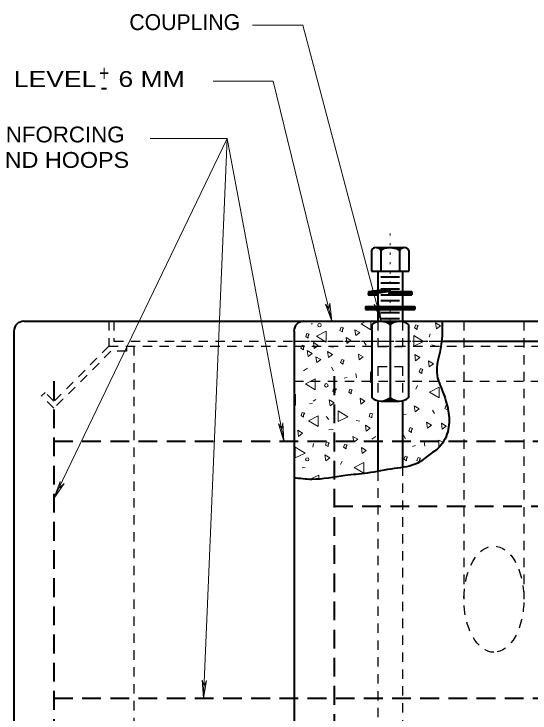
# Model space of a CAD drawing. Extents: x 312583 to 312854, y 144419 to 144597.
# Drawn here: x 312622.62 to 312647.35, y 144453.61 to 144487.12 of the extents above; entities that cross this region are included whole.
import ezdxf

# ---------------------------------------------------------------- set-up
doc = ezdxf.new("R2010")
doc.units = 0
doc.header["$LTSCALE"] = 0.3
for name, pattern in [('DOTTED', [1.5, 0.3, -1.2]), ('MEDIUM_DASHED', [4.5, 3, -1.5]), ('SHORT_DASHED', [2.7, 1.5, -1.2])]:
    doc.linetypes.add(name, pattern=pattern)
doc.layers.add('1', color=7, linetype='Continuous', lineweight=13)

msp = doc.modelspace()

# ---------------------------------------------------------------- linework, layer by layer
at = {"layer": '1'}
for p, q in [((312636.46, 144486.5936), (312634.0486, 144486.5936)), ((312636.46, 144486.5936), (312640.2097, 144472.3914)), ((312635.0366, 144483.8976), (312632.1687, 144483.8976)), ((312635.0366, 144483.8976), (312637.856, 144472.3914)), ((312632.8382, 144481.1516), (312624.539, 144463.8891)), ((312632.8382, 144481.1516), (312629.1475, 144481.1516)), ((312632.8382, 144481.1516), (312631.6997, 144454.3134)), ((312632.8382, 144481.1516), (312635.556, 144466.6414)), ((312637.5528, 144473.2095), (312637.7151, 144472.9649)), ((312637.852, 144472.3891), (312637.5528, 144473.2095)), ((312637.7562, 144473.2557), (312637.7151, 144472.9649)), ((312637.852, 144472.3891), (312637.7562, 144473.2557)), ((312639.8758, 144473.2008), (312640.0527, 144472.9636)), ((312640.2109, 144472.3948), (312639.8758, 144473.2008)), ((312640.0881, 144473.2553), (312640.0527, 144472.9636)), ((312640.2109, 144472.3948), (312640.0881, 144473.2553)), ((312636.8594, 144472.2611), (312636.9207, 144472.2611)), ((312639.7267, 144471.9851), (312639.7267, 144472.3914)), ((312642.571, 144471.7858), (312642.5097, 144471.6324)), ((312637.7947, 144471.1571), (312637.948, 144471.1724)), ((312639.397, 144471.3948), (312639.4967, 144471.2491)), ((312642.64, 144471.2568), (312642.8087, 144471.2184)), ((312641.5284, 144470.8044), (312641.536, 144470.8044)), ((312637.833, 144470.1834), (312637.925, 144470.0148)), ((312636.683, 144470.1374), (312636.499, 144470.0071)), ((312639.006, 144469.8921), (312639.029, 144469.6774)), ((312639.7727, 144469.9304), (312639.7114, 144469.9688)), ((312638.4387, 144469.6544), (312638.5844, 144469.7004)), ((312641.9577, 144469.3094), (312641.881, 144469.1331)), ((312636.9514, 144468.5658), (312637.0817, 144468.6348)), ((312636.0544, 144468.4048), (312636.108, 144468.3741)), ((312636.7827, 144468.4278), (312636.9284, 144468.4584)), ((312643.3914, 144468.2514), (312643.399, 144468.2591)), ((312637.5877, 144467.8298), (312637.7104, 144467.6764)), ((312641.2677, 144467.9218), (312641.421, 144467.9371)), ((312642.6707, 144468.1211), (312642.7704, 144467.9754)), ((312635.5083, 144467.5166), (312635.4538, 144467.2303)), ((312635.5524, 144466.647), (312635.5083, 144467.5166)), ((312639.0214, 144467.6381), (312639.19, 144467.5998)), ((312635.3005, 144467.4807), (312635.4538, 144467.2303)), ((312635.5524, 144466.647), (312635.3005, 144467.4807)), ((312637.7027, 144467.1781), (312637.9174, 144467.1934)), ((312639.9567, 144466.8714), (312639.7727, 144466.7334)), ((312641.2907, 144466.9251), (312641.3827, 144466.7488)), ((312636.9437, 144466.3501), (312636.9667, 144466.5341)), ((312642.2797, 144466.6184), (312642.3027, 144466.4038)), ((312642.985, 144466.6951), (312642.985, 144466.3654)), ((312643.169, 144466.5878), (312642.985, 144466.6951)), ((312641.7124, 144466.3808), (312641.858, 144466.4268)), ((312638.339, 144465.6908), (312638.27, 144465.5221)), ((312642.0574, 144465.6754), (312642.0574, 144465.7444)), ((312636.43, 144465.3688), (312636.5757, 144465.3764)), ((312624.539, 144463.8891), (312624.8304, 144464.7094)), ((312624.539, 144463.8891), (312625.022, 144464.6098)), ((312624.8304, 144464.7094), (312624.8074, 144464.4104)), ((312625.022, 144464.6098), (312624.8074, 144464.4104)), ((312631.6387, 144455.1846), (312631.731, 144454.9032)), ((312631.6991, 144454.3137), (312631.6387, 144455.1846)), ((312631.6991, 144454.3137), (312631.853, 144455.173)), ((312631.853, 144455.173), (312631.731, 144454.9032))]:
    msp.add_line(p, q, dxfattribs=at)
at = {"layer": '1', "linetype": 'DOTTED'}
msp.add_line((312640.6467, 144476.6004), (312640.6467, 144472.3914), dxfattribs=at)
at = {"layer": '1', "lineweight": 40}
for p, q in [((312639.972, 144475.9258), (312641.3214, 144475.9258)), ((312639.7497, 144475.7878), (312639.7497, 144474.7911)), ((312640.202, 144475.7878), (312640.202, 144474.7911)), ((312641.099, 144475.7878), (312641.099, 144474.7911)), ((312641.5437, 144475.7878), (312641.5437, 144474.7911)), ((312639.7497, 144474.7911), (312641.5437, 144474.7911)), ((312640.0487, 144474.7911), (312640.0487, 144472.3914)), ((312641.2447, 144474.7911), (312641.2447, 144472.3914)), ((312640.202, 144474.5151), (312641.099, 144474.5151)), ((312640.202, 144474.2314), (312641.099, 144474.2314)), ((312640.202, 144473.9478), (312641.099, 144473.9478)), ((312639.6117, 144473.8098), (312639.6117, 144473.6641)), ((312640.202, 144473.6641), (312641.099, 144473.6641)), ((312640.5624, 144473.6641), (312641.6894, 144473.6641)), ((312640.6007, 144473.8098), (312641.6894, 144473.8098)), ((312641.6894, 144473.8021), (312641.6894, 144473.6641)), ((312640.202, 144473.3804), (312641.099, 144473.3804)), ((312639.466, 144473.0968), (312641.8274, 144473.0968)), ((312639.466, 144473.0968), (312639.466, 144472.9588)), ((312639.466, 144473.0661), (312641.8274, 144473.0661)), ((312639.466, 144473.0278), (312641.8274, 144473.0278)), ((312639.466, 144472.9894), (312641.8274, 144472.9894)), ((312639.466, 144472.9588), (312641.8274, 144472.9588)), ((312641.8274, 144473.0968), (312641.8274, 144472.9588)), ((312640.202, 144472.8131), (312641.099, 144472.8131)), ((312640.202, 144472.5294), (312641.099, 144472.5294)), ((312623.0977, 144472.3914), (312636.5144, 144472.3914)), ((312636.5144, 144472.3914), (312654.7227, 144472.3914)), ((312639.7727, 144472.2304), (312639.7727, 144468.7268)), ((312640.0487, 144472.3914), (312641.2447, 144472.3914)), ((312640.2097, 144472.3914), (312641.0837, 144472.3914)), ((312640.6467, 144472.3914), (312640.6467, 144468.5658)), ((312641.5284, 144472.2304), (312641.5284, 144468.7268)), ((312622.6224, 144471.9161), (312622.6224, 144429.2664)), ((312636.039, 144471.9161), (312636.039, 144448.7628)), ((312643.0924, 144471.4331), (312648.1217, 144471.4331)), ((312640.0487, 144468.5581), (312640.0487, 144465.1924)), ((312640.2097, 144468.5658), (312641.0837, 144468.5658)), ((312641.2447, 144468.5581), (312641.2447, 144465.4224))]:
    msp.add_line(p, q, dxfattribs=at)
at = {"layer": '1', "linetype": 'SHORT_DASHED', "lineweight": 25}
for p, q in [((312627.1687, 144472.3914), (312627.1687, 144471.1954)), ((312627.414, 144472.3914), (312627.414, 144471.4331)), ((312640.0487, 144472.3914), (312640.0487, 144471.1801)), ((312641.2447, 144472.3914), (312641.2447, 144471.1801)), ((312644.181, 144472.3914), (312644.181, 144459.0668)), ((312647.056, 144472.3914), (312647.056, 144459.0668)), ((312627.1687, 144471.1954), (312624.539, 144468.5581)), ((312627.1687, 144471.1954), (312664.0684, 144471.1954)), ((312627.414, 144471.4331), (312663.8307, 144471.4331)), ((312628.012, 144471.1954), (312628.012, 144470.9578)), ((312628.3724, 144471.1954), (312628.3724, 144429.2664)), ((312636.039, 144471.4331), (312643.0924, 144471.4331)), ((312640.0487, 144471.1801), (312641.2447, 144471.1801)), ((312627.2684, 144470.9578), (312624.539, 144468.2208)), ((312628.012, 144470.9578), (312627.2684, 144470.9578)), ((312640.0487, 144470.2294), (312641.2447, 144470.2294)), ((312640.0487, 144470.2294), (312640.0487, 144468.5811)), ((312641.2447, 144470.2294), (312641.2447, 144468.5811)), ((312636.039, 144469.5164), (312655.2057, 144469.5164)), ((312624.1097, 144468.9798), (312623.941, 144468.8111)), ((312624.539, 144468.5581), (312624.1097, 144468.9798)), ((312624.539, 144468.2208), (312623.941, 144468.8111)), ((312640.0487, 144465.1924), (312640.0487, 144436.6878)), ((312641.2447, 144465.4224), (312641.2447, 144436.6878))]:
    msp.add_line(p, q, dxfattribs=at)
at = {"layer": '1', "linetype": 'MEDIUM_DASHED', "lineweight": 40}
for p, q in [((312624.539, 144469.5164), (312624.539, 144432.1414)), ((312637.9557, 144469.7541), (312637.9557, 144448.7628)), ((312624.539, 144466.6414), (312666.7057, 144466.6414)), ((312637.9557, 144463.5288), (312653.289, 144463.5288)), ((312624.539, 144454.3134), (312666.7057, 144454.3134))]:
    msp.add_line(p, q, dxfattribs=at)
at = {"layer": '1', "lineweight": 40}
for points in [[(312640.0334, 144475.9258), (312640.5317, 144475.9181), (312640.4474, 144475.9028), (312640.3937, 144475.8951), (312640.294, 144475.8568), (312640.202, 144475.7954), (312640.1714, 144475.8491), (312640.1254, 144475.8798), (312640.0487, 144475.9181), (312640.4934, 144475.9181), (312640.363, 144475.8951), (312640.2787, 144475.8491), (312640.2097, 144475.8031), (312640.133, 144475.8721), (312640.0794, 144475.9104), (312640.4397, 144475.9104), (312640.317, 144475.8721), (312640.2097, 144475.8184), (312640.11, 144475.9028), (312640.3937, 144475.9104), (312640.202, 144475.8261), (312640.1254, 144475.8951), (312640.363, 144475.9028), (312640.1944, 144475.8414), (312640.1407, 144475.8951), (312640.3324, 144475.8951), (312640.202, 144475.8568), (312640.1637, 144475.8874), (312640.2787, 144475.8874), (312640.2097, 144475.8644), (312640.1867, 144475.8798), (312640.2404, 144475.8798), (312640.202, 144475.8721)], [(312641.2677, 144475.9258), (312640.7617, 144475.9181), (312640.846, 144475.9028), (312640.9074, 144475.8951), (312640.9994, 144475.8568), (312641.0914, 144475.7954), (312641.1297, 144475.8491), (312641.168, 144475.8798), (312641.2447, 144475.9181), (312640.8, 144475.9181), (312640.9304, 144475.8951), (312641.0224, 144475.8491), (312641.0914, 144475.8031), (312641.1604, 144475.8721), (312641.214, 144475.9104), (312640.8537, 144475.9104), (312640.9764, 144475.8721), (312641.0914, 144475.8184), (312641.191, 144475.9028), (312640.8997, 144475.9104), (312641.0914, 144475.8261), (312641.168, 144475.8951), (312640.9304, 144475.9028), (312641.099, 144475.8414), (312641.1527, 144475.8951), (312640.9687, 144475.8951), (312641.0914, 144475.8568), (312641.1297, 144475.8874), (312641.0147, 144475.8874), (312641.0837, 144475.8644), (312641.1067, 144475.8798), (312641.053, 144475.8798), (312641.0914, 144475.8721)], [(312639.6117, 144473.8098), (312640.6467, 144473.9478), (312640.5624, 144473.6641)], [(312640.0487, 144473.6641), (312639.6117, 144473.6794), (312639.627, 144473.7944), (312640.616, 144473.9248), (312640.5854, 144473.8174), (312640.041, 144473.7408), (312640.0334, 144473.6871), (312639.6347, 144473.7024), (312639.6424, 144473.7714), (312640.593, 144473.9018), (312640.57, 144473.8328), (312640.018, 144473.7408), (312640.0104, 144473.7024), (312639.65, 144473.7101), (312639.65, 144473.7484), (312640.5547, 144473.8788), (312640.5547, 144473.8558), (312640.0257, 144473.7561), (312639.9874, 144473.7408), (312639.88, 144473.7178), (312639.673, 144473.7331), (312640.5317, 144473.8634), (312639.811, 144473.7254)], [(312640.6007, 144473.8098), (312639.6117, 144473.6641), (312640.0487, 144473.6641)], [(312640.5854, 144473.6794), (312641.6664, 144473.6794), (312641.6664, 144473.7944), (312640.6237, 144473.7868), (312640.5854, 144473.7024), (312641.651, 144473.6948), (312641.6434, 144473.7714), (312640.6314, 144473.7638), (312640.6084, 144473.7101), (312641.628, 144473.7178), (312641.6127, 144473.7484), (312641.605, 144473.7561), (312640.639, 144473.7484), (312640.6237, 144473.7254), (312641.605, 144473.7331)], [(312640.3247, 144472.3838), (312640.9764, 144472.3838), (312640.8997, 144472.3684), (312640.8307, 144472.3531), (312640.7617, 144472.3224), (312640.7157, 144472.2994), (312640.6544, 144472.2534), (312640.6467, 144472.2458), (312640.524, 144472.3224), (312640.4167, 144472.3684), (312640.3554, 144472.3838), (312640.9304, 144472.3838), (312640.8844, 144472.3761), (312640.8307, 144472.3608), (312640.7617, 144472.3378), (312640.6927, 144472.2994), (312640.6697, 144472.2764), (312640.6467, 144472.2534), (312640.5394, 144472.3301), (312640.4167, 144472.3761), (312640.846, 144472.3761), (312640.7387, 144472.3378), (312640.6467, 144472.2764), (312640.4627, 144472.3684), (312640.8, 144472.3684), (312640.6467, 144472.2688), (312640.501, 144472.3608), (312640.7694, 144472.3608), (312640.6544, 144472.2994), (312640.5547, 144472.3531), (312640.731, 144472.3531), (312640.6467, 144472.3224), (312640.547, 144472.3454), (312640.6084, 144472.3071), (312640.6237, 144472.3454), (312640.639, 144472.2918), (312640.685, 144472.3378), (312640.708, 144472.3378), (312640.7387, 144472.3454)], [(312640.3247, 144468.5734), (312640.9764, 144468.5658), (312640.8997, 144468.5811), (312640.8307, 144468.6041), (312640.7617, 144468.6348), (312640.7157, 144468.6578), (312640.6544, 144468.7038), (312640.6467, 144468.7114), (312640.524, 144468.6348), (312640.4167, 144468.5888), (312640.3554, 144468.5734), (312640.9304, 144468.5734), (312640.8844, 144468.5811), (312640.8307, 144468.5888), (312640.7617, 144468.6194), (312640.6927, 144468.6578), (312640.6697, 144468.6731), (312640.6467, 144468.6961), (312640.5394, 144468.6271), (312640.4167, 144468.5811), (312640.846, 144468.5811), (312640.7387, 144468.6194), (312640.6467, 144468.6731), (312640.4627, 144468.5888), (312640.8, 144468.5811), (312640.6467, 144468.6884), (312640.501, 144468.5964), (312640.7694, 144468.5888), (312640.6544, 144468.6578), (312640.5547, 144468.6041), (312640.731, 144468.6041), (312640.6467, 144468.6271), (312640.547, 144468.6118), (312640.6084, 144468.6501), (312640.6237, 144468.6118), (312640.639, 144468.6654), (312640.685, 144468.6194), (312640.708, 144468.6194), (312640.7387, 144468.6118)]]:
    msp.add_lwpolyline(points, dxfattribs=at)
at = {"layer": '1'}
for points in [[(312639.5044, 144472.3914), (312639.259, 144472.2688), (312639.7267, 144471.9851)], [(312641.5284, 144472.0618), (312641.5744, 144472.1001), (312641.5284, 144472.1308)], [(312639.7114, 144469.9688), (312639.7114, 144469.4551), (312639.7727, 144469.4781)], [(312636.108, 144468.3741), (312636.108, 144468.8878), (312636.0467, 144468.8494)], [(312643.3377, 144468.3588), (312643.3224, 144468.3664), (312643.261, 144468.2131), (312643.3914, 144468.1441), (312643.3914, 144468.2514)], [(312642.0574, 144465.7444), (312642.1034, 144465.8288), (312641.9884, 144465.8594), (312641.927, 144465.7138), (312642.0344, 144465.6524)], [(312637.235, 144464.8398), (312637.235, 144465.0161), (312636.8517, 144464.8321)]]:
    msp.add_lwpolyline(points, dxfattribs=at)
for points in [[(312641.9424, 144472.1078), (312641.996, 144472.1844), (312641.8734, 144472.2228), (312641.8197, 144472.0694), (312641.9424, 144472.0004)], [(312642.8624, 144472.0311), (312643.054, 144472.1768), (312642.8164, 144472.3148)], [(312637.58, 144471.3948), (312637.58, 144471.9084), (312637.1124, 144471.6708)], [(312638.362, 144471.9928), (312638.4157, 144472.0771), (312638.293, 144472.1078), (312638.2394, 144471.9544), (312638.362, 144471.8854)], [(312638.9984, 144471.7014), (312639.1977, 144471.8471), (312638.96, 144471.9851)], [(312636.7214, 144471.6938), (312636.7674, 144471.7781), (312636.6524, 144471.8088), (312636.5987, 144471.6554), (312636.7214, 144471.5864)], [(312638.569, 144471.3258), (312638.7607, 144471.4714), (312638.5307, 144471.6171)], [(312641.7737, 144471.7091), (312641.7737, 144471.1954), (312642.2414, 144471.4254)], [(312636.4914, 144471.1341), (312636.545, 144471.2184), (312636.4224, 144471.2491), (312636.3687, 144471.0958), (312636.4914, 144471.0268)], [(312637.0127, 144471.0804), (312637.2044, 144471.2338), (312636.9744, 144471.3718)], [(312636.7137, 144470.7048), (312636.913, 144470.8504), (312636.6754, 144470.9884)], [(312637.695, 144470.6588), (312637.8867, 144470.8044), (312637.649, 144470.9424)], [(312637.1354, 144470.4058), (312637.327, 144470.5514), (312637.0894, 144470.6894)], [(312638.4004, 144470.4441), (312638.4464, 144470.5284), (312638.3314, 144470.5591), (312638.27, 144470.4134), (312638.4004, 144470.3368)], [(312639.167, 144470.5361), (312639.3587, 144470.6818), (312639.1287, 144470.8198)], [(312641.8657, 144470.4978), (312642.065, 144470.6511), (312641.8274, 144470.7891)], [(312642.5174, 144470.2064), (312642.7167, 144470.3521), (312642.479, 144470.4901)], [(312642.1647, 144469.9994), (312642.2107, 144470.0838), (312642.0957, 144470.1221), (312642.0344, 144469.9688), (312642.1647, 144469.8921)], [(312637.0587, 144469.1101), (312637.0587, 144469.6238), (312636.591, 144469.3861)], [(312638.017, 144469.0718), (312638.0707, 144469.1561), (312637.948, 144469.1868), (312637.8944, 144469.0411), (312638.017, 144468.9644)], [(312643.0004, 144468.7191), (312643.0004, 144469.2328), (312642.5327, 144468.9951)], [(312638.7837, 144469.0181), (312638.8297, 144469.1024), (312638.7147, 144469.1331), (312638.661, 144468.9874), (312638.7837, 144468.9108)], [(312637.764, 144468.3358), (312637.9557, 144468.4814), (312637.7257, 144468.6194)], [(312639.2437, 144468.4124), (312639.4354, 144468.5581), (312639.2054, 144468.6961)], [(312641.8427, 144468.0521), (312642.0344, 144468.1978), (312641.8044, 144468.3434)], [(312636.499, 144467.9064), (312636.5527, 144467.9831), (312636.43, 144468.0214), (312636.3764, 144467.8681), (312636.499, 144467.7991)], [(312637.2044, 144467.3391), (312637.2044, 144467.8528), (312636.7367, 144467.6151)], [(312638.155, 144468.0904), (312638.155, 144467.5768), (312638.6227, 144467.8144)], [(312639.765, 144467.8604), (312639.8187, 144467.9448), (312639.696, 144467.9831), (312639.6424, 144467.8298), (312639.765, 144467.7531)], [(312642.4407, 144467.2624), (312642.6324, 144467.4081), (312642.3947, 144467.5461)], [(312643.146, 144467.2164), (312643.3377, 144467.3621), (312643.1077, 144467.5078)], [(312636.2537, 144466.8714), (312636.453, 144467.0248), (312636.2154, 144467.1628)], [(312639.4967, 144467.1244), (312639.696, 144467.2701), (312639.4584, 144467.4081)], [(312641.674, 144467.1704), (312641.72, 144467.2548), (312641.605, 144467.2931), (312641.5437, 144467.1398), (312641.674, 144467.0631)], [(312638.9064, 144466.5878), (312639.098, 144466.7334), (312638.8604, 144466.8714)], [(312637.6797, 144466.4804), (312637.7257, 144466.5648), (312637.603, 144466.6031), (312637.5494, 144466.4498), (312637.6797, 144466.3808)], [(312638.546, 144466.3808), (312638.592, 144466.4651), (312638.477, 144466.5034), (312638.4157, 144466.3501), (312638.546, 144466.2811)], [(312636.1004, 144466.3501), (312636.1004, 144465.8364), (312636.568, 144466.0664)], [(312639.3127, 144466.0511), (312639.5044, 144466.1968), (312639.2667, 144466.3348)], [(312637.557, 144465.6984), (312637.7487, 144465.8441), (312637.5187, 144465.9898)], [(312641.4287, 144465.8058), (312641.4747, 144465.8901), (312641.3597, 144465.9284), (312641.2984, 144465.7751), (312641.4287, 144465.6984)], [(312639.3817, 144465.1004), (312639.3817, 144465.6141), (312638.914, 144465.3764)]]:
    msp.add_lwpolyline(points, close=True, dxfattribs=at)
for centre, radius in [((312637.261, 144472.2022), 0.0865), ((312637.5878, 144469.3176), 0.0865), ((312636.6707, 144465.7706), 0.0784)]:
    msp.add_circle(centre, radius, dxfattribs=at)
at = {"layer": '1', "lineweight": 40}
for centre, radius, start, end in [((312639.9733, 144475.6772), 0.2489, 25.60064, 154.39936), ((312640.6467, 144475.1425), 0.7836, 55.04559, 124.95441), ((312641.3201, 144475.6772), 0.2489, 25.60064, 154.39936), ((312623.0977, 144471.9132), 0.4792, 90, 180), ((312636.5144, 144471.9132), 0.4792, 90, 180), ((312640.2085, 144471.7103), 0.6817, 50.00693, 129.99306), ((312641.0848, 144471.7103), 0.6817, 50.00694, 129.99307), ((312640.2085, 144469.2472), 0.6817, 230.00694, 309.99307), ((312641.0848, 144469.2472), 0.6817, 230.00693, 309.99306)]:
    msp.add_arc(centre, radius, start, end, dxfattribs=at)
at = {"layer": '1', "linetype": 'SHORT_DASHED', "lineweight": 25}
msp.add_ellipse((312645.6185, 144459.0653), major_axis=(0, -2.5458), ratio=0.564653, dxfattribs=at)
at = {"layer": '1', "lineweight": 40}
msp.add_spline([(312643.1307, 144472.3914), (312643.0924, 144471.2721), (312642.9007, 144469.7771), (312643.1614, 144469.0258), (312643.4297, 144468.0981), (312643.4297, 144467.2011), (312643.0157, 144466.3731), (312642.4944, 144465.9668), (312641.9654, 144465.5911), (312640.846, 144465.3304), (312639.5427, 144465.1081), (312638.4924, 144464.9931), (312636.89, 144464.8091), (312636.039, 144464.8858)], degree=3, dxfattribs=at)

# ---------------------------------------------------------------- texts
at = {"layer": '1'}
for s, p in [('COUPLING', (312628.1502, 144486.3515)), ('-', (312626.7637, 144483.2517))]:
    msp.add_text(s, height=0.76, dxfattribs=at).set_placement(p)
for s, width, p in [('LEVEL   6 MM', 1.25, (312622.6139, 144483.6254)), ('+', 0.8, (312626.7037, 144483.9159)), ('15M REINFORCING', 1.05, (312618.0771, 144480.9652)), ('BARS AND HOOPS', 1.1, (312618.0771, 144479.7452))]:
    msp.add_text(s, height=0.76, dxfattribs=dict(at, width=width)).set_placement(p)

doc.saveas('drawing.dxf')
